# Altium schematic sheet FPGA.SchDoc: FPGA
size B; Date: 12/18/2013; DrawnBy: David McCoy; Engineer: David McCoy (Cospan Design); DocumentNumber: 3; Revision: C; SheetNumber: 3; SheetTotal: 10
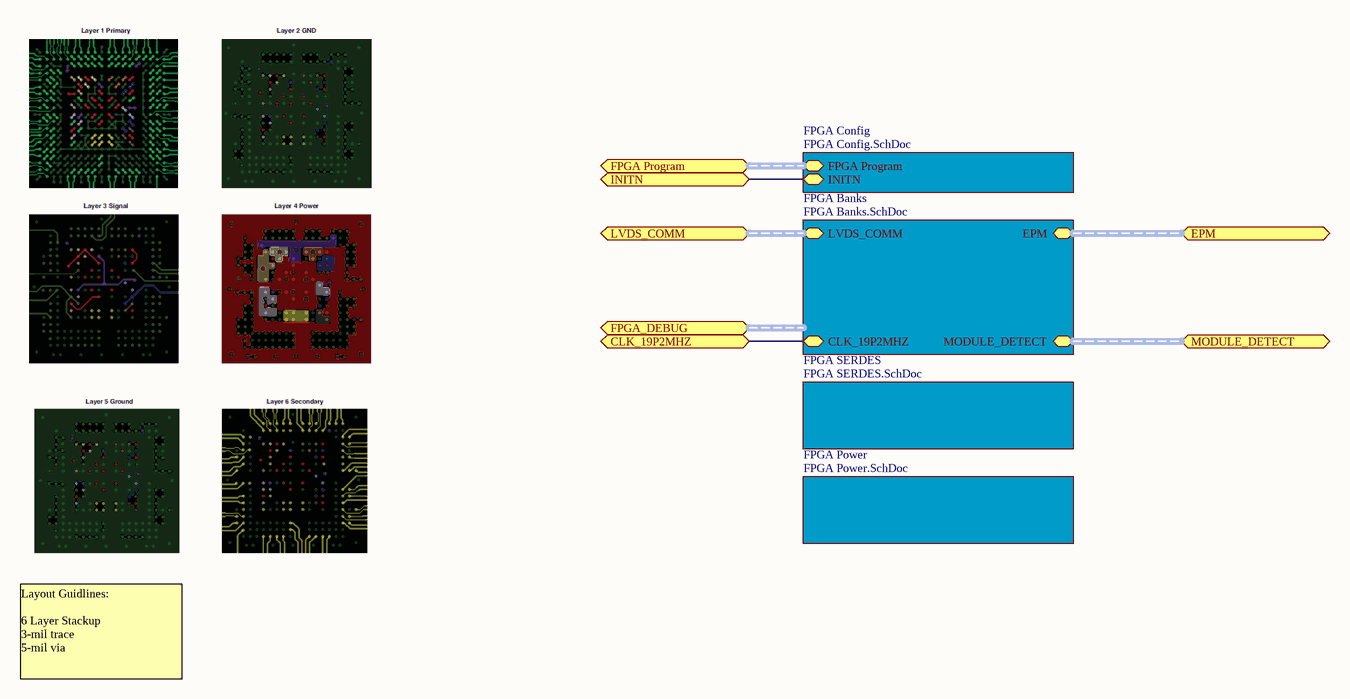
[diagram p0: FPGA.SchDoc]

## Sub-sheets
FPGA Banks = FPGA Banks.SchDoc: EPM (harness EPM_Harness), LVDS_COMM (harness LVDS_Comm_Harness), MODULE_DETECT (harness Module_Detect_Harness), CLK_19P2MHZ
FPGA Config = FPGA Config.SchDoc: FPGA Program (harness FPGA_Program_Harness), INITN
FPGA Power = FPGA Power.SchDoc: no entries
FPGA SERDES = FPGA SERDES.SchDoc: no entries

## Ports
CLK_19P2MHZ, EPM (harness EPM_Harness), FPGA Program (harness FPGA_Program_Harness), FPGA_DEBUG (harness FPGA_Debug_Harness), INITN, LVDS_COMM (harness LVDS_Comm_Harness), MODULE_DETECT (harness Module_Detect_Harness)

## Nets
CLK_19P2MHZ: port CLK_19P2MHZ, sheet FPGA Banks/CLK_19P2MHZ
INITN: port INITN, sheet FPGA Config/INITN

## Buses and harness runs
harness port EPM = sheet FPGA Banks/EPM
harness port FPGA Program = sheet FPGA Config/FPGA Program
harness port LVDS_COMM = sheet FPGA Banks/LVDS_COMM
harness port MODULE_DETECT = sheet FPGA Banks/MODULE_DETECT

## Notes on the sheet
- Layout Guidlines:
  6 Layer Stackup
  3-mil trace
  5-mil via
